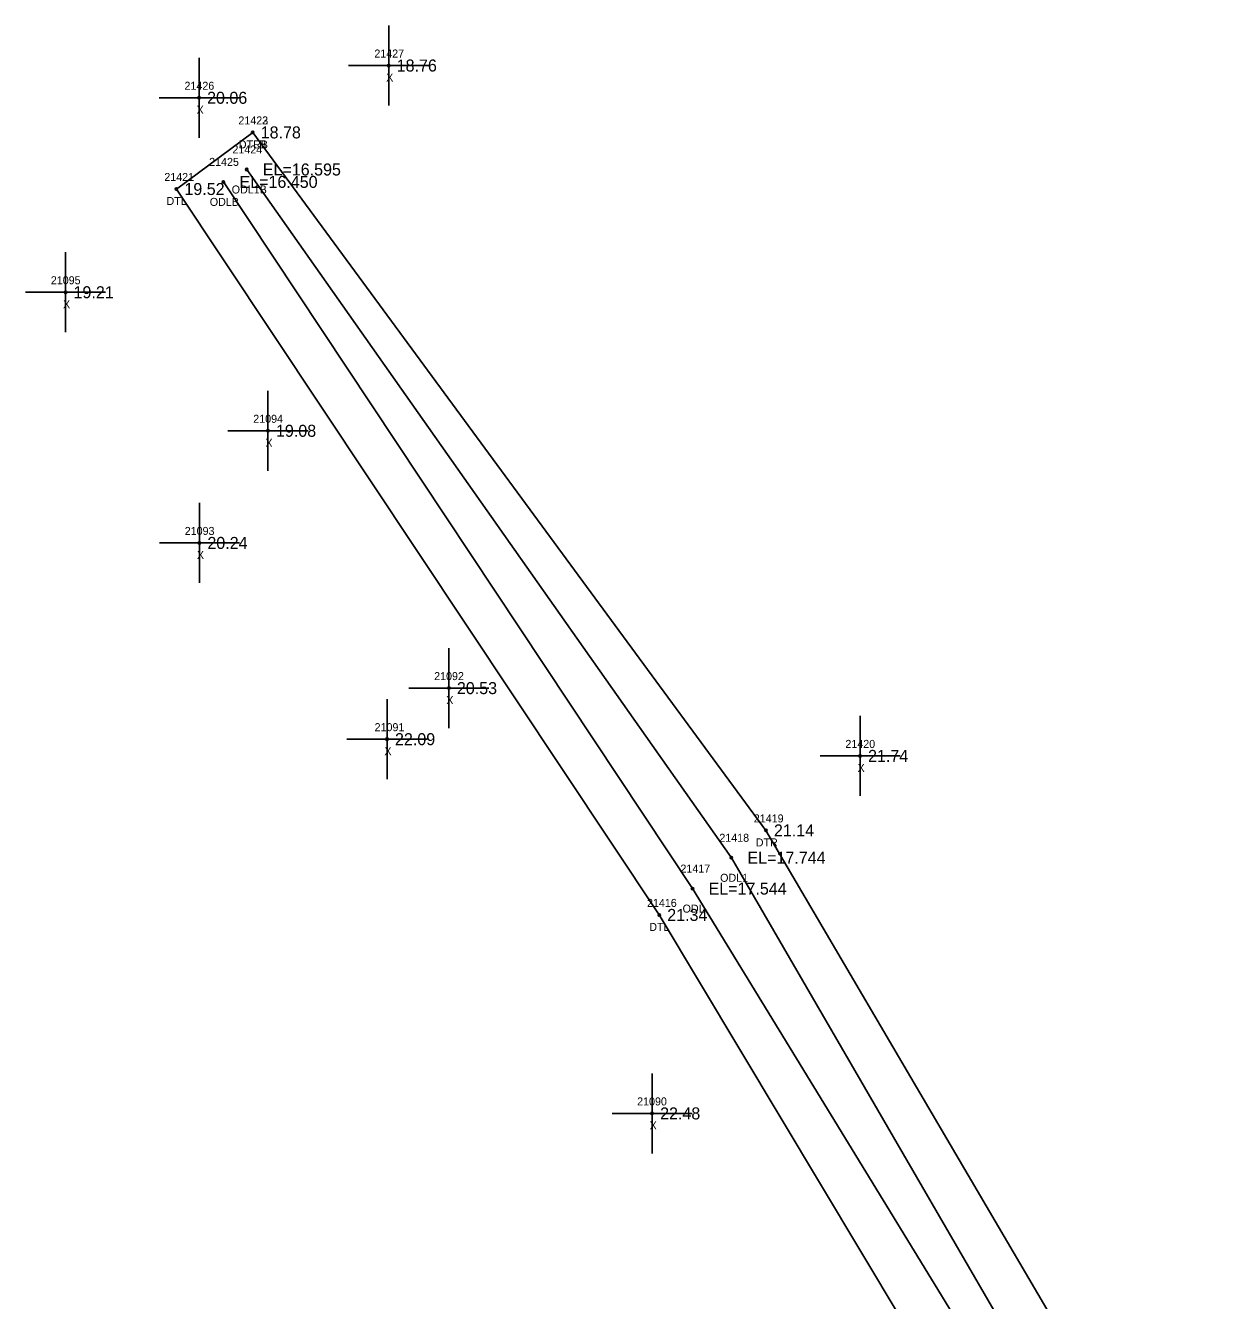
# Model space of a CAD drawing. Extents: x 2655177 to 2656219, y 761780 to 764748.
# Drawn here: x 2655177.4 to 2655327.5, y 762575 to 762734.3 of the extents above; entities that cross this region are included whole.
import ezdxf

# ---------------------------------------------------------------- set-up
doc = ezdxf.new("R2010")
doc.units = 0
for name, color, linetype in [('RD_EX_H2O', 7, 'Continuous'), ('RD_EX_H2O_txCode', 7, 'Continuous'), ('RD_EX_Misc', 7, 'Continuous'), ('RD_EX_Misc_txCode', 7, 'Continuous'), ('RD_EX_TX_H2O_ELEV', 7, 'Continuous'), ('RD_EX_TX_Misc_ELEV', 7, 'Continuous'), ('RD_SMD_Locator', 7, 'Continuous')]:
    doc.layers.add(name, color=color, linetype=linetype)

msp = doc.modelspace()

# ---------------------------------------------------------------- linework, layer by layer
at = {"layer": 'RD_EX_H2O'}
for points in [[(2655472.03, 762316.1), (2655422.66, 762374.06), (2655364.12, 762460.66), (2655307.09, 762538.82), (2655256.59, 762623.14), (2655196.27, 762713.84), (2655205.8, 762720.91)], [(2655477.51, 762339.55), (2655436.55, 762384.38), (2655373.64, 762467.97), (2655320.48, 762547.58), (2655269.92, 762633.7), (2655205.8, 762720.91)], [(2655477.37, 762324.35), (2655429.88, 762379.43), (2655369.67, 762464.93), (2655315.46, 762544.29), (2655265.61, 762630.28), (2655205.06, 762716.28)], [(2655476.38, 762321.27), (2655427.48, 762377.64), (2655367.29, 762463.1), (2655312.28, 762542.21), (2655260.75, 762626.43), (2655202.15, 762714.73)]]:
    msp.add_lwpolyline(points, dxfattribs=at)
at = {"layer": 'RD_EX_Misc'}
for p, q in [((2655222.79, 762724.27), (2655222.79, 762734.27)), ((2655199.1, 762720.24), (2655199.1, 762730.24)), ((2655217.79, 762729.27), (2655227.79, 762729.27)), ((2655194.1, 762725.24), (2655204.1, 762725.24)), ((2655182.42, 762695.94), (2655182.42, 762705.94)), ((2655177.42, 762700.94), (2655187.42, 762700.94)), ((2655207.71, 762678.63), (2655207.71, 762688.63)), ((2655202.71, 762683.63), (2655212.71, 762683.63)), ((2655199.14, 762664.62), (2655199.14, 762674.62)), ((2655194.14, 762669.62), (2655204.14, 762669.62)), ((2655230.31, 762646.48), (2655230.31, 762656.48)), ((2655225.31, 762651.48), (2655235.31, 762651.48)), ((2655222.58, 762640.1), (2655222.58, 762650.1)), ((2655281.68, 762638.01), (2655281.68, 762648.01)), ((2655217.58, 762645.1), (2655227.58, 762645.1)), ((2655276.68, 762643.01), (2655286.68, 762643.01)), ((2655255.7, 762593.34), (2655255.7, 762603.34)), ((2655250.7, 762598.34), (2655260.7, 762598.34))]:
    msp.add_line(p, q, dxfattribs=at)
at = {"layer": 'RD_SMD_Locator'}
for centre in [(2655222.79, 762729.27), (2655199.1, 762725.24), (2655205.8, 762720.91), (2655205.8, 762720.91), (2655205.06, 762716.28), (2655202.15, 762714.73), (2655196.27, 762713.84), (2655182.42, 762700.94), (2655207.71, 762683.63), (2655199.14, 762669.62), (2655230.31, 762651.48), (2655222.58, 762645.1), (2655281.68, 762643.01), (2655269.92, 762633.7), (2655265.61, 762630.28), (2655260.75, 762626.43), (2655256.59, 762623.14), (2655255.7, 762598.34)]:
    msp.add_circle(centre, 0.15, dxfattribs=at)

# ---------------------------------------------------------------- texts
at = {"layer": 'RD_EX_H2O_txCode'}
for s, p in [('21422', (2655204.01, 762721.91)), ('21423', (2655204.01, 762721.91)), ('DTRB', (2655204.06, 762718.91)), ('DTLB', (2655204.08, 762718.91)), ('21425', (2655200.36, 762716.73)), ('21424', (2655203.27, 762718.28)), ('21421', (2655194.76, 762714.84)), ('ODL1B', (2655203.18, 762713.28)), ('DTL', (2655195.03, 762711.84)), ('ODLB', (2655200.44, 762711.73)), ('21419', (2655268.41, 762634.7)), ('21418', (2655264.1, 762632.28)), ('DTR', (2655268.65, 762631.7)), ('21417', (2655259.24, 762628.43)), ('ODL1', (2655264.2, 762627.28)), ('21416', (2655255.06, 762624.14)), ('ODL', (2655259.51, 762623.43)), ('DTL', (2655255.35, 762621.14))]:
    msp.add_text(s, height=1, dxfattribs=at).set_placement(p)
at = {"layer": 'RD_EX_Misc_txCode'}
for s, p in [('21427', (2655221, 762730.27)), ('X', (2655222.48, 762727.27)), ('21426', (2655197.28, 762726.24)), ('X', (2655198.79, 762723.24)), ('21095', (2655180.58, 762701.94)), ('X', (2655182.1, 762698.94)), ('21094', (2655205.87, 762684.63)), ('X', (2655207.39, 762681.63)), ('21093', (2655197.31, 762670.62)), ('X', (2655198.83, 762667.62)), ('21092', (2655228.47, 762652.48)), ('X', (2655229.99, 762649.48)), ('21091', (2655221.03, 762646.1)), ('21420', (2655279.85, 762644.01)), ('X', (2655222.26, 762643.1)), ('X', (2655281.37, 762641.01)), ('21090', (2655253.83, 762599.34)), ('X', (2655255.39, 762596.34))]:
    msp.add_text(s, height=1, dxfattribs=at).set_placement(p)
at = {"layer": 'RD_EX_TX_H2O_ELEV'}
for s, p in [('18.78', (2655206.8, 762720.16)), ('18.78', (2655206.8, 762720.16)), ('EL=16.595', (2655207.06, 762715.53)), ('19.52', (2655197.27, 762713.09)), ('EL=16.450', (2655204.15, 762713.98)), ('21.14', (2655270.92, 762632.95)), ('EL=17.744', (2655267.61, 762629.53)), ('EL=17.544', (2655262.75, 762625.68)), ('21.34', (2655257.59, 762622.39))]:
    msp.add_text(s, height=1.5, dxfattribs=at).set_placement(p)
at = {"layer": 'RD_EX_TX_Misc_ELEV'}
for s, p in [('18.76', (2655223.79, 762728.52)), ('20.06', (2655200.1, 762724.49)), ('19.21', (2655183.42, 762700.19)), ('19.08', (2655208.71, 762682.88)), ('20.24', (2655200.14, 762668.87)), ('20.53', (2655231.31, 762650.73)), ('22.09', (2655223.58, 762644.35)), ('21.74', (2655282.68, 762642.26)), ('22.48', (2655256.7, 762597.59))]:
    msp.add_text(s, height=1.5, dxfattribs=at).set_placement(p)

doc.saveas('drawing.dxf')
